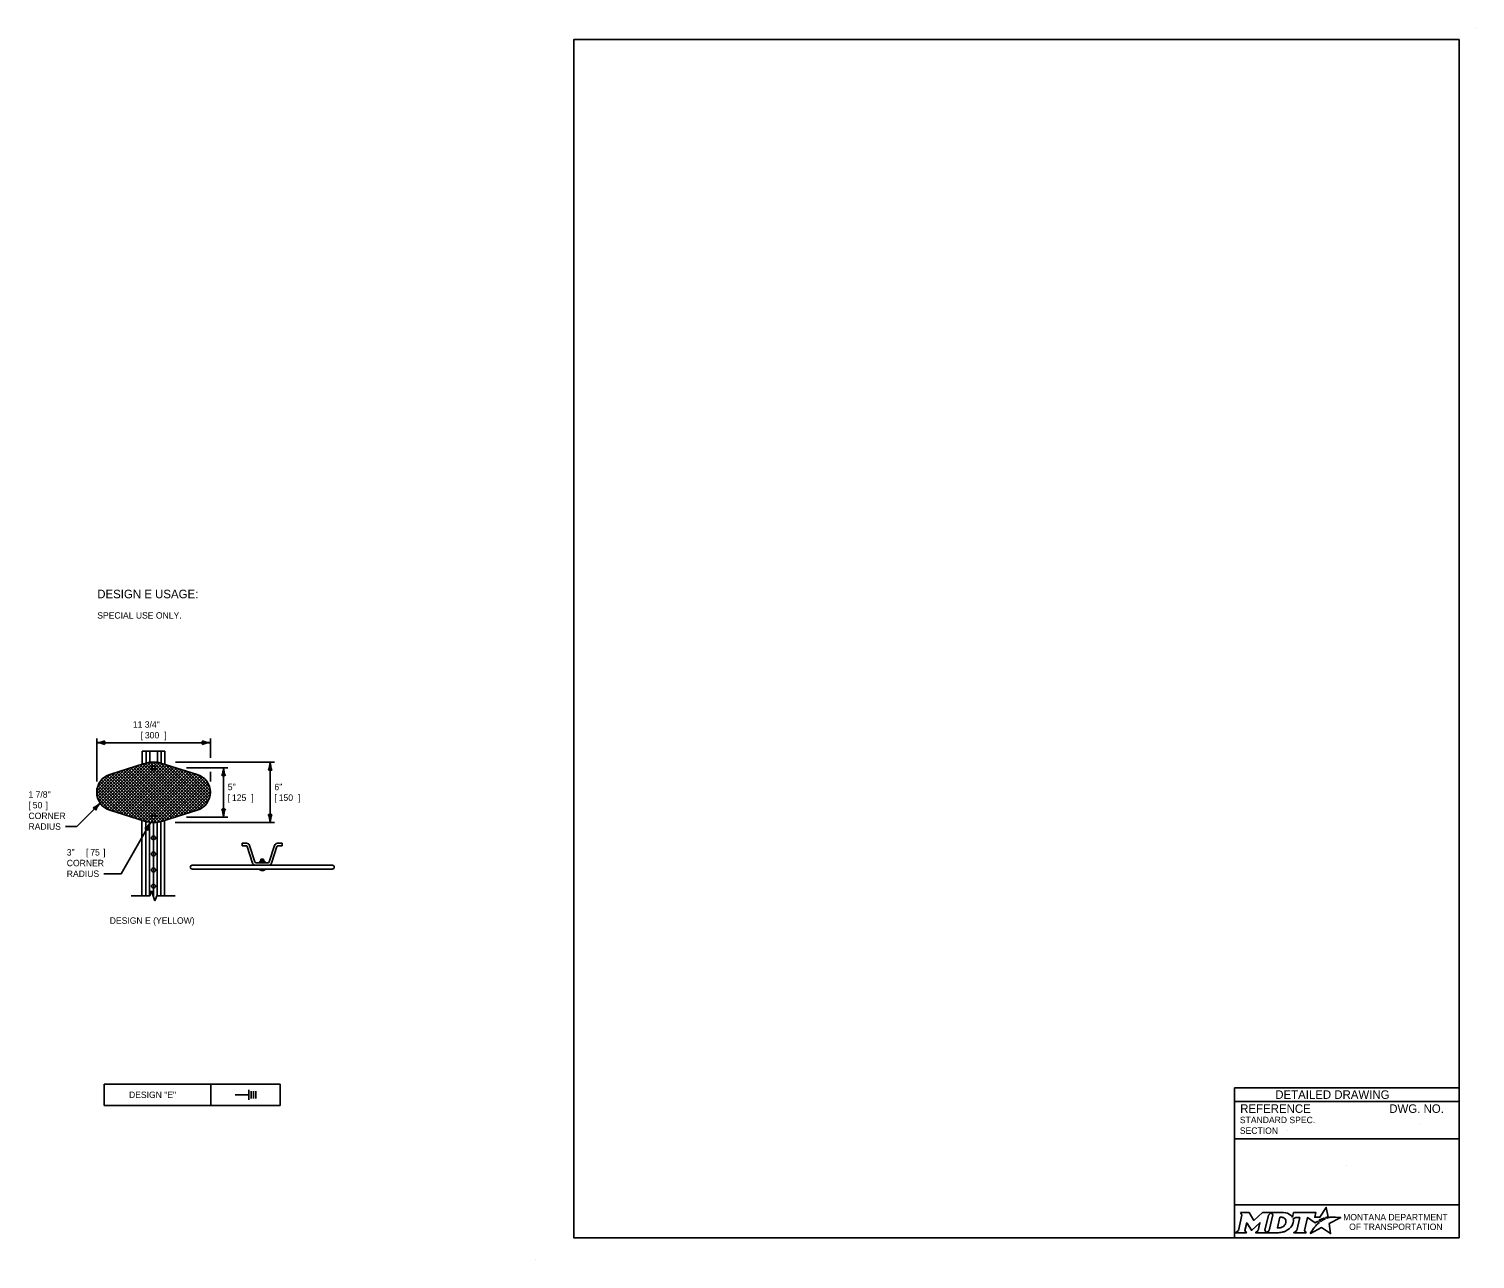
# Model space of a CAD drawing. Extents: x 49991.4 to 50021, y 49987.6 to 50011.4.
# Drawn here: x 49995.24 to 50008.76, y 49999.86 to 50011.36 of the extents above; entities that cross this region are included whole.
import ezdxf

# ---------------------------------------------------------------- set-up
doc = ezdxf.new("R2010")
doc.units = 0
for name, color, linetype in [('Level 1', 7, 'Continuous'), ('Level 2', 7, 'Continuous'), ('Level 3', 7, 'Continuous'), ('Level 5', 7, 'Continuous'), ('Level 6', 7, 'Continuous')]:
    doc.layers.add(name, color=color, linetype=linetype)

msp = doc.modelspace()

# ---------------------------------------------------------------- linework, layer by layer
at = {"layer": 'Level 1'}
for p, q in [((50008.765, 50011.363), (50008.765, 50011.363)), ((49995.936, 50004.093), (49996.346, 50004.501)), ((49995.952, 50004.08), (49996.381, 50004.507)), ((49995.971, 50004.069), (49996.412, 50004.508)), ((49995.991, 50004.06), (49996.44, 50004.506)), ((49996.014, 50004.053), (49996.465, 50004.502)), ((49996.3, 50004.61), (49996.513, 50004.61)), ((49996.3, 50004.488), (49996.3, 50004.61)), ((49996.336, 50004.499), (49996.336, 50004.61)), ((49996.799, 50004.053), (49996.351, 50004.502)), ((49996.371, 50004.506), (49996.371, 50004.61)), ((49996.822, 50004.061), (49996.376, 50004.506)), ((49996.842, 50004.069), (49996.404, 50004.508)), ((49996.861, 50004.08), (49996.434, 50004.507)), ((49996.442, 50004.506), (49996.442, 50004.61)), ((49996.877, 50004.093), (49996.469, 50004.501)), ((49996.475, 50004.5), (49996.814, 50004.394)), ((49996.477, 50004.499), (49996.477, 50004.61)), ((49996.513, 50004.488), (49996.513, 50004.61)), ((49995.875, 50004.238), (49996.047, 50004.409)), ((49995.876, 50004.209), (49996.09, 50004.423)), ((49995.88, 50004.184), (49996.133, 50004.436)), ((49995.881, 50004.274), (49996.004, 50004.396)), ((49995.887, 50004.162), (49996.176, 50004.449)), ((49995.896, 50004.142), (49996.219, 50004.463)), ((49995.908, 50004.124), (49996.262, 50004.476)), ((49995.921, 50004.108), (49996.305, 50004.489)), ((49996.378, 50003.945), (49995.952, 50004.372)), ((49996.409, 50003.944), (49995.97, 50004.383)), ((49996.437, 50003.945), (49995.991, 50004.392)), ((49995.999, 50004.394), (49996.319, 50004.494)), ((49996.463, 50003.949), (49996.013, 50004.399)), ((49996.036, 50004.046), (49996.488, 50004.496)), ((49996.486, 50003.955), (49996.036, 50004.406)), ((49996.508, 50003.962), (49996.058, 50004.413)), ((49996.059, 50004.039), (49996.511, 50004.489)), ((49996.531, 50003.969), (49996.08, 50004.42)), ((49996.081, 50004.032), (49996.533, 50004.482)), ((49996.103, 50004.025), (49996.555, 50004.475)), ((49996.553, 50003.976), (49996.103, 50004.427)), ((49996.576, 50003.983), (49996.125, 50004.434)), ((49996.126, 50004.018), (49996.578, 50004.468)), ((49996.148, 50004.011), (49996.6, 50004.461)), ((49996.598, 50003.99), (49996.148, 50004.441)), ((49996.62, 50003.997), (49996.17, 50004.447)), ((49996.171, 50004.004), (49996.623, 50004.454)), ((49996.643, 50004.004), (49996.193, 50004.454)), ((49996.193, 50003.997), (49996.645, 50004.447)), ((49996.665, 50004.011), (49996.215, 50004.461)), ((49996.215, 50003.99), (49996.668, 50004.44)), ((49996.688, 50004.018), (49996.238, 50004.468)), ((49996.238, 50003.983), (49996.69, 50004.433)), ((49996.71, 50004.025), (49996.26, 50004.475)), ((49996.26, 50003.976), (49996.713, 50004.426)), ((49996.732, 50004.032), (49996.282, 50004.482)), ((49996.283, 50003.969), (49996.735, 50004.419)), ((49996.755, 50004.039), (49996.305, 50004.489)), ((49996.305, 50003.962), (49996.758, 50004.412)), ((49996.777, 50004.046), (49996.327, 50004.496)), ((49996.328, 50003.955), (49996.78, 50004.405)), ((49996.351, 50003.949), (49996.803, 50004.398)), ((49996.377, 50003.945), (49996.825, 50004.39)), ((49996.405, 50003.944), (49996.845, 50004.381)), ((49996.436, 50003.945), (49996.863, 50004.37)), ((49996.892, 50004.108), (49996.512, 50004.488)), ((49996.905, 50004.124), (49996.554, 50004.475)), ((49996.917, 50004.142), (49996.597, 50004.462)), ((49996.926, 50004.162), (49996.64, 50004.448)), ((49996.933, 50004.185), (49996.683, 50004.435)), ((49996.937, 50004.21), (49996.725, 50004.422)), ((49996.937, 50004.239), (49996.768, 50004.409)), ((49996.931, 50004.275), (49996.811, 50004.395)), ((49996.087, 50004.03), (49995.876, 50004.242)), ((49996.13, 50004.017), (49995.88, 50004.267)), ((49996.173, 50004.003), (49995.887, 50004.29)), ((49996.216, 50003.99), (49995.896, 50004.31)), ((49996.259, 50003.976), (49995.907, 50004.328)), ((49996.302, 50003.963), (49995.92, 50004.344)), ((49996.343, 50003.951), (49995.935, 50004.359)), ((49996.472, 50003.951), (49996.88, 50004.357)), ((49996.514, 50003.964), (49996.894, 50004.342)), ((49996.557, 50003.977), (49996.907, 50004.326)), ((49996.6, 50003.991), (49996.918, 50004.307)), ((49996.643, 50004.004), (49996.927, 50004.287)), ((49996.686, 50004.018), (49996.934, 50004.264)), ((49996.729, 50004.031), (49996.937, 50004.238)), ((49996.045, 50004.044), (49995.875, 50004.213)), ((49996.002, 50004.057), (49995.882, 50004.177)), ((49996.772, 50004.045), (49996.937, 50004.209)), ((49996.815, 50004.058), (49996.929, 50004.171)), ((49995.998, 50004.058), (49996.322, 50003.957)), ((49996.298, 50003.259), (49996.298, 50003.964)), ((49996.491, 50003.957), (49996.815, 50004.058)), ((49996.51, 50003.259), (49996.51, 50003.963)), ((49996.333, 50003.259), (49996.333, 50003.953)), ((49996.369, 50003.259), (49996.369, 50003.946)), ((49996.44, 50003.259), (49996.44, 50003.946)), ((49996.475, 50003.259), (49996.475, 50003.952)), ((49997.234, 50003.726), (49997.234, 50003.75)), ((49997.277, 50003.75), (49997.234, 50003.75)), ((49997.272, 50003.726), (49997.234, 50003.726)), ((49997.333, 50003.565), (49997.283, 50003.718)), ((49997.354, 50003.576), (49997.304, 50003.73)), ((49997.489, 50003.576), (49997.538, 50003.729)), ((49997.51, 50003.565), (49997.559, 50003.718)), ((49997.566, 50003.75), (49997.609, 50003.75)), ((49997.609, 50003.726), (49997.571, 50003.726)), ((49997.609, 50003.726), (49997.609, 50003.75)), ((49997.478, 50003.568), (49997.365, 50003.568)), ((49997.402, 50003.582), (49997.402, 50003.568)), ((49997.402, 50003.582), (49997.446, 50003.582)), ((49997.41, 50003.6), (49997.435, 50003.6)), ((49997.41, 50003.582), (49997.41, 50003.6)), ((49997.41, 50003.591), (49997.435, 50003.591)), ((49997.415, 50003.596), (49997.431, 50003.596)), ((49997.415, 50003.587), (49997.431, 50003.587)), ((49997.415, 50003.582), (49997.415, 50003.568)), ((49997.431, 50003.582), (49997.431, 50003.568)), ((49997.435, 50003.582), (49997.435, 50003.6)), ((49997.446, 50003.582), (49997.446, 50003.568)), ((49998.079, 50003.545), (49996.767, 50003.545)), ((49998.079, 50003.509), (49996.767, 50003.509)), ((49999.977, 49999.862), (49999.977, 49999.862))]:
    msp.add_line(p, q, dxfattribs=at)
msp.add_lwpolyline([(50008.615, 50011.263), (50000.336, 50011.263), (50000.336, 50000.062), (50008.615, 50000.062)], close=True, dxfattribs=at)
for centre in [(49996.406, 50004.456), (49996.406, 50003.995), (49996.406, 50003.8), (49996.406, 50003.65), (49996.406, 50003.5), (49996.406, 50003.349)]:
    msp.add_circle(centre, 0.0188, dxfattribs=at)
for centre, radius, start, end in [((49996.407, 50004.226), 0.282, 76.0341, 108.2499), ((49996.051, 50004.226), 0.176, 107.2511, 252.5744), ((49996.762, 50004.226), 0.176, 287.4259, 72.7489), ((49996.406, 50004.226), 0.282, 252.5672, 287.4328), ((49997.272, 50003.715), 0.0117, 17.8891, 90), ((49997.276, 50003.721), 0.0293, 17.888, 90), ((49997.566, 50003.721), 0.0293, 90, 162.1111), ((49997.571, 50003.715), 0.0117, 90, 162.1109), ((49997.361, 50003.574), 0.0293, 197.8891, 270), ((49997.365, 50003.58), 0.0117, 197.8889, 270), ((49997.478, 50003.58), 0.0117, 270, 342.1111), ((49997.482, 50003.574), 0.0293, 270, 342.1109), ((49996.767, 50003.527), 0.0176, 90, 270), ((49997.424, 50003.537), 0.0425, 219.8388, 320.1612), ((49998.079, 50003.527), 0.0176, 270, 90)]:
    msp.add_arc(centre, radius, start, end, dxfattribs=at)
at = {"layer": 'Level 2'}
for p, q in [((49995.945, 50001.298), (49995.945, 50001.498)), ((49995.945, 50001.498), (49997.59, 50001.498)), ((49996.941, 50001.298), (49996.941, 50001.498)), ((49997.298, 50001.398), (49997.169, 50001.398)), ((49997.298, 50001.351), (49997.298, 50001.445)), ((49997.319, 50001.365), (49997.319, 50001.431)), ((49997.341, 50001.365), (49997.341, 50001.431)), ((49997.363, 50001.365), (49997.363, 50001.431)), ((49997.59, 50001.298), (49997.59, 50001.498)), ((50008.615, 50001.462), (50006.515, 50001.462)), ((50006.515, 50001.462), (50006.515, 50000.062)), ((49995.945, 50001.298), (49997.59, 50001.298)), ((50008.615, 50001.337), (50006.515, 50001.337)), ((50008.251, 50001.122), (50008.251, 50001.122)), ((50008.615, 50000.987), (50006.515, 50000.987)), ((50007.009, 50001.063), (50007.009, 50001.063)), ((50007.565, 50000.738), (50007.565, 50000.738)), ((50008.615, 50000.369), (50006.515, 50000.369))]:
    msp.add_line(p, q, dxfattribs=at)
for points in [[(50007.377, 50000.245), (50007.367, 50000.25), (50007.378, 50000.253), (50007.39, 50000.255), (50007.373, 50000.345), (50007.313, 50000.254), (50007.266, 50000.253), (50007.276, 50000.297), (50007.067, 50000.297), (50007.057, 50000.255), (50007.051, 50000.263)], [(50006.57, 50000.297), (50006.584, 50000.274), (50006.551, 50000.131), (50006.525, 50000.108), (50006.627, 50000.108), (50006.613, 50000.131), (50006.629, 50000.201), (50006.673, 50000.132), (50006.678, 50000.132), (50006.753, 50000.202), (50006.737, 50000.13), (50006.712, 50000.108), (50006.814, 50000.108), (50006.8, 50000.132), (50006.833, 50000.274)], [(50006.833, 50000.274), (50006.859, 50000.297), (50006.776, 50000.297), (50006.697, 50000.224), (50006.652, 50000.297), (50006.57, 50000.297)], [(50006.972, 50000.297), (50006.859, 50000.297), (50006.873, 50000.275), (50006.839, 50000.131), (50006.814, 50000.108), (50006.925, 50000.108)], [(50006.996, 50000.211), (50006.995, 50000.203), (50006.992, 50000.193), (50006.988, 50000.185), (50006.982, 50000.178), (50006.976, 50000.171), (50006.968, 50000.164), (50006.959, 50000.16), (50006.95, 50000.156), (50006.941, 50000.154), (50006.932, 50000.153), (50006.916, 50000.153), (50006.94, 50000.253), (50006.956, 50000.253), (50006.963, 50000.252), (50006.971, 50000.25), (50006.977, 50000.247), (50006.983, 50000.243), (50006.988, 50000.238), (50006.992, 50000.232), (50006.995, 50000.226), (50006.996, 50000.218), (50006.996, 50000.215), (50006.996, 50000.211)], [(50007.064, 50000.238), (50007.088, 50000.251), (50007.125, 50000.251), (50007.097, 50000.131), (50007.069, 50000.108), (50007.185, 50000.108), (50007.168, 50000.131), (50007.196, 50000.251), (50007.268, 50000.2), (50007.289, 50000.215), (50007.309, 50000.204)], [(50007.253, 50000.148), (50007.237, 50000.124), (50007.233, 50000.116), (50007.227, 50000.107), (50007.225, 50000.103), (50007.33, 50000.156), (50007.414, 50000.101), (50007.401, 50000.194), (50007.508, 50000.252), (50007.458, 50000.253), (50007.428, 50000.253), (50007.407, 50000.254), (50007.401, 50000.252), (50007.396, 50000.251), (50007.387, 50000.249), (50007.377, 50000.245)], [(50007.327, 50000.217), (50007.324, 50000.215), (50007.306, 50000.225), (50007.316, 50000.231), (50007.32, 50000.233), (50007.329, 50000.237), (50007.335, 50000.239), (50007.343, 50000.243), (50007.35, 50000.245), (50007.362, 50000.238), (50007.358, 50000.236), (50007.353, 50000.233), (50007.349, 50000.231), (50007.344, 50000.228), (50007.342, 50000.227), (50007.339, 50000.225), (50007.337, 50000.224), (50007.334, 50000.222), (50007.332, 50000.221), (50007.329, 50000.219), (50007.327, 50000.217)], [(50006.97, 50000.116), (50006.979, 50000.118), (50006.992, 50000.124), (50007.012, 50000.135)], [(50007.267, 50000.164), (50007.267, 50000.164)]]:
    msp.add_lwpolyline(points, dxfattribs=at)
for centre, radius, start, end in [((50006.951, 50000.236), 0.118, 300.9103, 339.1383), ((50006.995, 50000.219), 0.0709, 339.5329, 15.8582)]:
    msp.add_arc(centre, radius, start, end, dxfattribs=at)
for centre, major_axis, ratio, start_param, end_param in [((50006.97, 50000.25), (0.0834, -0.0037), 0.568097, 0.61298, 1.570796), ((50007.026, 50000.257), (0.0361, -0.0295), 0.469099, 1.225588, 1.570796), ((50007.276, 50000.174), (-0.0098, -0.0102), 0.016458, 3.141593, 6.279097), ((50007.297, 50000.194), (-0.0112, -0.0097), 0.021651, 3.157348, 6.283185), ((50006.925, 50000.257), (0, 0.148), 0.987302, 3.139398, 3.456847), ((50007.26, 50000.156), (-0.00694, -0.00806), 0.008222, 0, 3.137361)]:
    msp.add_ellipse(centre, major_axis=major_axis, ratio=ratio, start_param=start_param, end_param=end_param, dxfattribs=at)
at = {"layer": 'Level 3'}
for p, q in [((49995.875, 50004.326), (49995.875, 50004.73)), ((49995.875, 50004.69), (49996.938, 50004.69)), ((49996.938, 50004.548), (49996.938, 50004.73)), ((49996.613, 50004.508), (49997.537, 50004.508)), ((49997.497, 50003.944), (49997.497, 50004.508)), ((49996.715, 50004.456), (49997.101, 50004.456)), ((49996.938, 50004.326), (49996.938, 50004.416)), ((49997.061, 50003.995), (49997.061, 50004.456)), ((49995.908, 50004.124), (49995.689, 50003.906)), ((49996.714, 50003.995), (49997.101, 50003.995)), ((49995.689, 50003.906), (49995.584, 50003.906)), ((49996.378, 50003.945), (49996.103, 50003.465)), ((49996.61, 50003.944), (49997.537, 50003.944)), ((49996.103, 50003.465), (49995.942, 50003.465))]:
    msp.add_line(p, q, dxfattribs=at)
for centre, radius, start, end in [((49995.863, 50004.923), 0.233, 272.8273, 292.0772), ((49995.866, 50004.468), 0.222, 67.456, 87.6395), ((49996.003, 50004.69), 0.0548, 162.1388, 197.8612), ((49996.947, 50004.912), 0.222, 247.456, 267.6395), ((49996.81, 50004.69), 0.0548, 342.1388, 17.8612), ((49996.949, 50004.457), 0.233, 92.8273, 112.0772), ((49997.275, 50004.517), 0.222, 337.456, 357.6395), ((49997.73, 50004.519), 0.233, 182.8273, 202.0772), ((49996.839, 50004.465), 0.222, 337.456, 357.6395), ((49997.061, 50004.328), 0.0548, 72.1388, 107.8612), ((49997.294, 50004.467), 0.233, 182.8273, 202.0772), ((49997.497, 50004.38), 0.0548, 72.1388, 107.8612), ((49995.757, 50004.287), 0.222, 292.456, 312.6395), ((49996.08, 50003.967), 0.233, 137.8273, 157.0772), ((49995.817, 50004.033), 0.0548, 27.1388, 62.8612), ((49997.061, 50004.123), 0.0548, 252.1388, 287.8612), ((49996.828, 50003.984), 0.233, 2.8273, 22.0772), ((49997.283, 50003.986), 0.222, 157.456, 177.6395), ((49997.497, 50004.072), 0.0548, 252.1388, 287.8612), ((49997.264, 50003.932), 0.233, 2.8273, 22.0772), ((49997.719, 50003.934), 0.222, 157.456, 177.6395), ((49996.19, 50004.063), 0.222, 307.6181, 327.8017), ((49996.315, 50003.834), 0.0548, 42.301, 78.0233), ((49996.586, 50003.839), 0.233, 152.9894, 172.2393)]:
    msp.add_arc(centre, radius, start, end, dxfattribs=at)
at = {"layer": 'Level 5'}
msp.add_line((49996.406, 50003.252), (49996.406, 50003.944), dxfattribs=at)
at = {"layer": 'Level 6'}
for p, q in [((49996.388, 50003.304), (49996.372, 50003.259)), ((49996.388, 50003.304), (49996.404, 50003.259)), ((49996.198, 50003.259), (49996.372, 50003.259)), ((49996.404, 50003.259), (49996.42, 50003.213)), ((49996.436, 50003.259), (49996.42, 50003.213)), ((49996.436, 50003.259), (49996.61, 50003.259))]:
    msp.add_line(p, q, dxfattribs=at)

# ---------------------------------------------------------------- texts
at = {"layer": 'Level 2'}
for s, height, p in [('DESIGN E USAGE:', 0.08, (49995.88, 50006.04)), ('SPECIAL USE ONLY.', 0.06, (49995.88, 50005.85)), ('11 3/4"', 0.06, (49996.213, 50004.83)), ('[', 0.06, (49996.287, 50004.73)), ('300', 0.06, (49996.326, 50004.73)), (']', 0.06, (49996.506, 50004.73)), ('1 7/8"', 0.06, (49995.237, 50004.176)), ('5"', 0.06, (49997.101, 50004.246)), ('6"', 0.06, (49997.537, 50004.246)), ('[', 0.06, (49995.237, 50004.076)), ('50', 0.06, (49995.277, 50004.076)), (']', 0.06, (49995.397, 50004.076)), ('[', 0.06, (49997.101, 50004.146)), ('125', 0.06, (49997.14, 50004.146)), (']', 0.06, (49997.32, 50004.146)), ('[', 0.06, (49997.537, 50004.146)), ('150', 0.06, (49997.577, 50004.146)), (']', 0.06, (49997.757, 50004.146)), ('CORNER', 0.06, (49995.237, 50003.976)), ('RADIUS', 0.06, (49995.237, 50003.876)), ('3" ', 0.06, (49995.595, 50003.635)), ('[', 0.06, (49995.775, 50003.635)), ('75', 0.06, (49995.815, 50003.635)), (']', 0.06, (49995.935, 50003.635)), ('CORNER', 0.06, (49995.595, 50003.535)), ('RADIUS', 0.06, (49995.595, 50003.435)), ('DESIGN E (YELLOW)', 0.06, (49995.997, 50002.997)), ('DESIGN "E"', 0.06, (49996.177, 50001.368)), ('DETAILED DRAWING', 0.0799, (50006.896, 50001.36)), ('REFERENCE', 0.08, (50006.568, 50001.229)), ('DWG. NO.', 0.08, (50007.962, 50001.229)), ('STANDARD SPEC.', 0.06, (50006.565, 50001.133)), ('SECTION', 0.06, (50006.565, 50001.033)), ('MONTANA DEPARTMENT', 0.06, (50007.531, 50000.224)), ('OF TRANSPORTATION', 0.06, (50007.587, 50000.134))]:
    msp.add_text(s, height=height, dxfattribs=at).set_placement(p)

doc.saveas('drawing.dxf')
